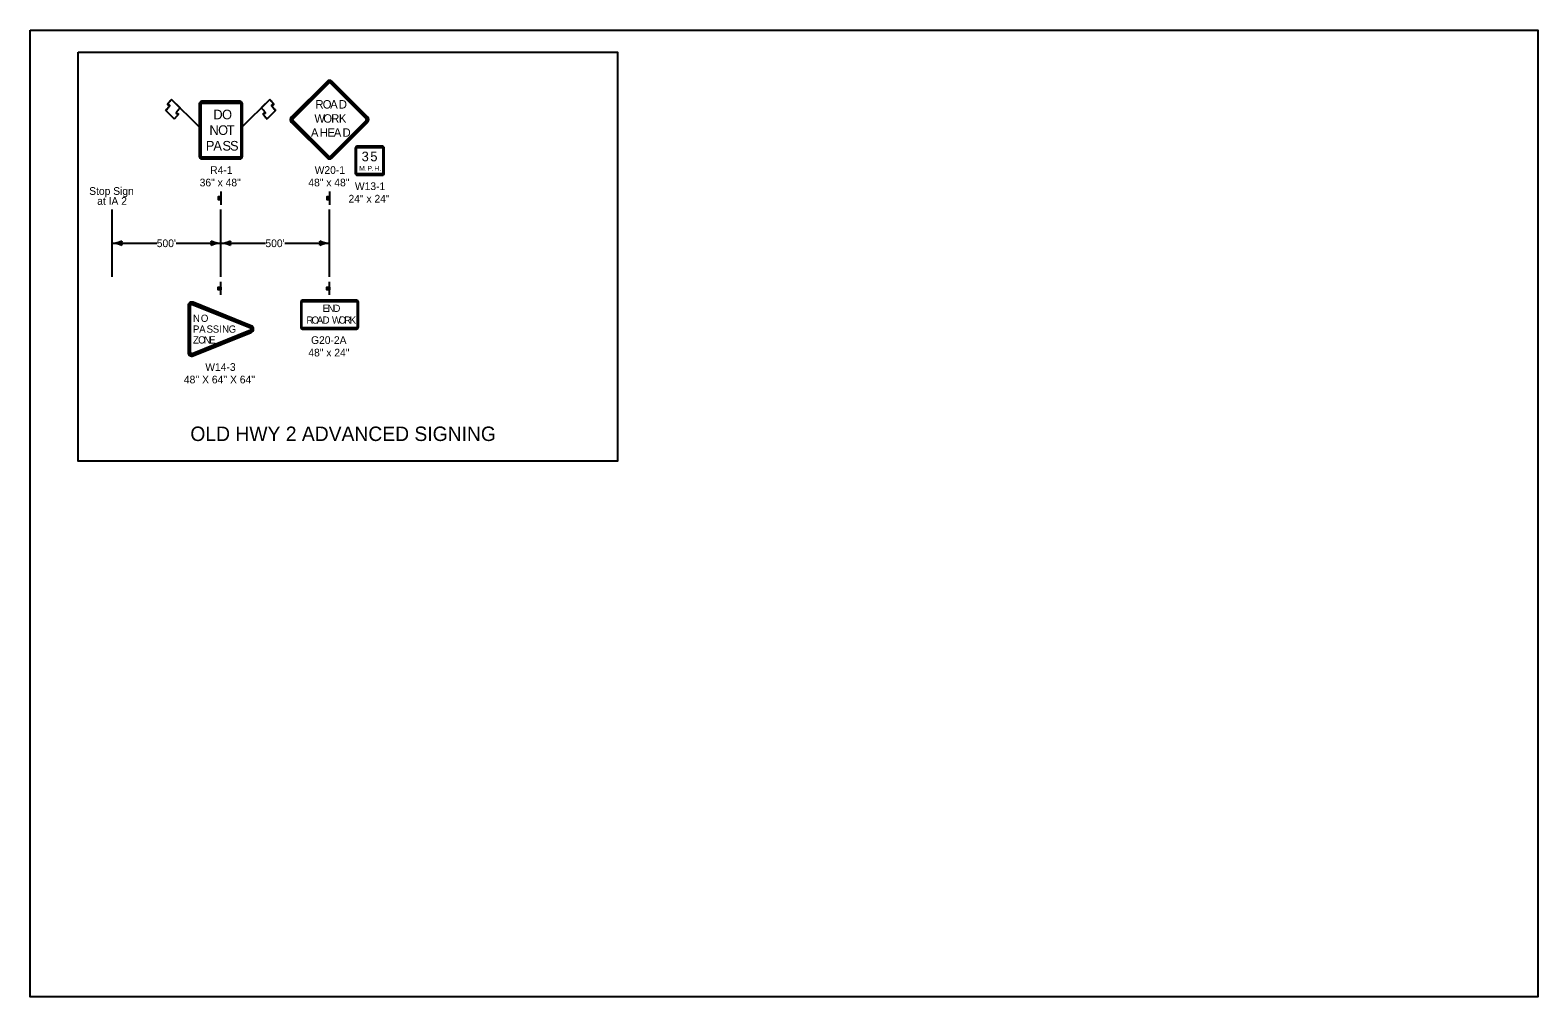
# Model space of a CAD drawing. Extents: x -2134934 to -2119606, y -2139046 to -2137036.
# Drawn here: x -2125529 to -2122394, y -2139046 to -2137036 of the extents above; entities that cross this region are included whole.
import ezdxf

# ---------------------------------------------------------------- set-up
doc = ezdxf.new("R2010")
doc.units = 0
for name, color, linetype in [('Default', 7, 'Continuous'), ('dsnStdLabel', 7, 'Continuous'), ('Level 2', 7, 'Continuous'), ('Level 5', 7, 'Continuous')]:
    doc.layers.add(name, color=color, linetype=linetype)

msp = doc.modelspace()

# ---------------------------------------------------------------- linework, layer by layer
at = {"layer": 'Default'}
msp.add_lwpolyline([(-2125529.5, -2137035.9), (-2122394.5, -2137035.9), (-2122394.5, -2139045.9), (-2125529.5, -2139045.9)], close=True, dxfattribs=at)
at = {"layer": 'dsnStdLabel'}
for p, q in [((-2124912.2, -2137142.5), (-2124986.5, -2137216.7)), ((-2124910.9, -2137143.8), (-2124908.7, -2137146)), ((-2124905.1, -2137146), (-2124902.9, -2137143.8)), ((-2124827.4, -2137216.7), (-2124901.6, -2137142.5)), ((-2125177.9, -2137237.3), (-2125235.3, -2137180)), ((-2125235.3, -2137180), (-2125217.6, -2137197.7)), ((-2125093.6, -2137183.8), (-2125172.3, -2137183.8)), ((-2125172.3, -2137187.5), (-2125172.3, -2137185.3)), ((-2125093.6, -2137185.3), (-2125093.6, -2137187.5)), ((-2125088.7, -2137237.3), (-2125031.3, -2137180)), ((-2125031.3, -2137180), (-2125049, -2137197.6)), ((-2125230, -2137220.6), (-2125247.6, -2137203)), ((-2125177.9, -2137189.4), (-2125177.9, -2137298.1)), ((-2125176.4, -2137189.4), (-2125174.2, -2137189.4)), ((-2125091.7, -2137189.4), (-2125089.5, -2137189.4)), ((-2125087.9, -2137298.1), (-2125087.9, -2137189.4)), ((-2125036.6, -2137220.6), (-2125019, -2137203)), ((-2124982.9, -2137220.2), (-2124985.1, -2137218)), ((-2124828.7, -2137218), (-2124830.9, -2137220.2)), ((-2124986.5, -2137227.3), (-2124912.2, -2137301.6)), ((-2124985.1, -2137226), (-2124982.9, -2137223.8)), ((-2124901.6, -2137301.6), (-2124827.4, -2137227.3)), ((-2124830.9, -2137223.8), (-2124828.7, -2137226)), ((-2124853.4, -2137281.2), (-2124853.4, -2137333.7)), ((-2124852.5, -2137281.2), (-2124850.9, -2137281.2)), ((-2124797.1, -2137277.4), (-2124849.6, -2137277.4)), ((-2124849.6, -2137279.9), (-2124849.6, -2137278.3)), ((-2124797.1, -2137278.3), (-2124797.1, -2137279.9)), ((-2124795.9, -2137281.2), (-2124794.3, -2137281.2)), ((-2124793.4, -2137333.7), (-2124793.4, -2137281.2)), ((-2125174.2, -2137298.1), (-2125176.4, -2137298.1)), ((-2125172.3, -2137302.2), (-2125172.3, -2137300)), ((-2125172.3, -2137303.8), (-2125093.6, -2137303.8)), ((-2125093.6, -2137300), (-2125093.6, -2137302.2)), ((-2125089.5, -2137298.1), (-2125091.7, -2137298.1)), ((-2124908.7, -2137298), (-2124910.9, -2137300.2)), ((-2124902.9, -2137300.2), (-2124905.1, -2137298)), ((-2124850.9, -2137333.7), (-2124852.5, -2137333.7)), ((-2124849.6, -2137336.5), (-2124849.6, -2137334.9)), ((-2124849.6, -2137337.4), (-2124797.1, -2137337.4)), ((-2124797.1, -2137334.9), (-2124797.1, -2137336.5)), ((-2124794.3, -2137333.7), (-2124795.9, -2137333.7)), ((-2125200.9, -2137608.7), (-2125200.9, -2137706.4)), ((-2125199, -2137608.7), (-2125195.9, -2137608.7)), ((-2125192.4, -2137606.3), (-2125191.2, -2137603.4)), ((-2125069.7, -2137650.6), (-2125190.5, -2137601.7)), ((-2124966.9, -2137601.2), (-2124966.9, -2137653.7)), ((-2124966, -2137601.2), (-2124964.4, -2137601.2)), ((-2124850.7, -2137597.4), (-2124963.2, -2137597.4)), ((-2124963.2, -2137599.9), (-2124963.2, -2137598.3)), ((-2124850.7, -2137598.3), (-2124850.7, -2137599.9)), ((-2124849.4, -2137601.2), (-2124847.8, -2137601.2)), ((-2124846.9, -2137653.7), (-2124846.9, -2137601.2)), ((-2125070.4, -2137652.3), (-2125071.6, -2137655.2)), ((-2124964.4, -2137653.7), (-2124966, -2137653.7)), ((-2124963.2, -2137656.5), (-2124963.2, -2137654.9)), ((-2124963.2, -2137657.4), (-2124850.7, -2137657.4)), ((-2124850.7, -2137654.9), (-2124850.7, -2137656.5)), ((-2124847.8, -2137653.7), (-2124849.4, -2137653.7)), ((-2125190.5, -2137713.4), (-2125069.7, -2137664.5)), ((-2125071.6, -2137659.8), (-2125070.4, -2137662.7)), ((-2125195.9, -2137706.4), (-2125199, -2137706.4)), ((-2125191.2, -2137711.6), (-2125192.4, -2137708.7))]:
    msp.add_line(p, q, dxfattribs=at)
for points in [[(-2125429.5, -2137081.6), (-2124308.2, -2137081.6), (-2124308.2, -2137932.2), (-2125429.5, -2137932.2)], [(-2124910.9, -2137143.8), (-2124985.1, -2137218), (-2124982.9, -2137220.2), (-2124908.7, -2137146), (-2124910.9, -2137143.8)], [(-2124828.7, -2137218), (-2124902.9, -2137143.8), (-2124905.1, -2137146), (-2124830.9, -2137220.2), (-2124828.7, -2137218)], [(-2125093.6, -2137185.3), (-2125172.3, -2137185.3), (-2125172.3, -2137187.5), (-2125093.6, -2137187.5), (-2125093.6, -2137185.3)], [(-2125176.4, -2137189.4), (-2125176.4, -2137298.1), (-2125174.2, -2137298.1), (-2125174.2, -2137189.4), (-2125176.4, -2137189.4)], [(-2125089.5, -2137298.1), (-2125089.5, -2137189.4), (-2125091.7, -2137189.4), (-2125091.7, -2137298.1), (-2125089.5, -2137298.1)], [(-2124985.1, -2137226), (-2124910.9, -2137300.2), (-2124908.7, -2137298), (-2124982.9, -2137223.8), (-2124985.1, -2137226)], [(-2124902.9, -2137300.2), (-2124828.7, -2137226), (-2124830.9, -2137223.8), (-2124905.1, -2137298), (-2124902.9, -2137300.2)], [(-2124852.5, -2137281.2), (-2124852.5, -2137333.7), (-2124850.9, -2137333.7), (-2124850.9, -2137281.2), (-2124852.5, -2137281.2)], [(-2124797.1, -2137278.3), (-2124849.6, -2137278.3), (-2124849.6, -2137279.9), (-2124797.1, -2137279.9), (-2124797.1, -2137278.3)], [(-2124794.3, -2137333.7), (-2124794.3, -2137281.2), (-2124795.9, -2137281.2), (-2124795.9, -2137333.7), (-2124794.3, -2137333.7)], [(-2125172.3, -2137302.2), (-2125093.6, -2137302.2), (-2125093.6, -2137300), (-2125172.3, -2137300), (-2125172.3, -2137302.2)], [(-2124849.6, -2137336.5), (-2124797.1, -2137336.5), (-2124797.1, -2137334.9), (-2124849.6, -2137334.9), (-2124849.6, -2137336.5)], [(-2125199, -2137608.7), (-2125199, -2137706.4), (-2125195.9, -2137706.4), (-2125195.9, -2137608.7), (-2125199, -2137608.7)], [(-2125070.4, -2137652.3), (-2125191.2, -2137603.4), (-2125192.4, -2137606.3), (-2125071.6, -2137655.2), (-2125070.4, -2137652.3)], [(-2124966, -2137601.2), (-2124966, -2137653.7), (-2124964.4, -2137653.7), (-2124964.4, -2137601.2), (-2124966, -2137601.2)], [(-2124850.7, -2137598.3), (-2124963.2, -2137598.3), (-2124963.2, -2137599.9), (-2124850.7, -2137599.9), (-2124850.7, -2137598.3)], [(-2124847.8, -2137653.7), (-2124847.8, -2137601.2), (-2124849.4, -2137601.2), (-2124849.4, -2137653.7), (-2124847.8, -2137653.7)], [(-2124963.2, -2137656.5), (-2124850.7, -2137656.5), (-2124850.7, -2137654.9), (-2124963.2, -2137654.9), (-2124963.2, -2137656.5)], [(-2125191.2, -2137711.6), (-2125070.4, -2137662.7), (-2125071.6, -2137659.8), (-2125192.4, -2137708.7), (-2125191.2, -2137711.6)]]:
    msp.add_lwpolyline(points, close=True, dxfattribs=at)
for centre, radius, start, end in [((-2124906.9, -2137147.8), 7.5, 45, 134.9997), ((-2124906.9, -2137147.8), 5.62, 45, 134.9997), ((-2124906.9, -2137147.8), 2.5, 45, 134.9997), ((-2125172.3, -2137189.4), 5.62, 90.0002, 179.9998), ((-2125172.3, -2137189.4), 4.06, 90.0002, 179.9998), ((-2125172.3, -2137189.4), 1.87, 90.0002, 179.9998), ((-2125093.6, -2137189.4), 5.62, 0, 90.0002), ((-2125093.6, -2137189.4), 4.06, 0, 90.0002), ((-2125093.6, -2137189.4), 1.87, 0, 90.0002), ((-2124981.2, -2137222), 7.5, 134.9997, 225), ((-2124981.2, -2137222), 5.62, 134.9997, 225), ((-2124832.7, -2137222), 5.62, 315.0002, 44.9998), ((-2124832.7, -2137222), 7.5, 315.0002, 44.9998), ((-2124981.2, -2137222), 2.5, 134.9997, 225), ((-2124832.7, -2137222), 2.5, 315.0002, 44.9998), ((-2124849.6, -2137281.2), 3.75, 90.0002, 179.9998), ((-2124849.6, -2137281.2), 2.81, 90.0002, 179.9998), ((-2124849.6, -2137281.2), 1.25, 90.0002, 179.9998), ((-2124797.1, -2137281.2), 3.75, 0, 90.0002), ((-2124797.1, -2137281.2), 2.81, 0, 90.0002), ((-2124797.1, -2137281.2), 1.25, 0, 90.0002), ((-2125172.3, -2137298.1), 5.62, 179.9998, 270.0001), ((-2125172.3, -2137298.1), 4.06, 179.9998, 270.0001), ((-2125172.3, -2137298.1), 1.87, 179.9998, 270.0001), ((-2125093.6, -2137298.1), 5.62, 270.0001, 0.0003), ((-2125093.6, -2137298.1), 4.06, 270.0001, 0.0003), ((-2125093.6, -2137298.1), 1.87, 270.0001, 0.0003), ((-2124906.9, -2137296.3), 7.5, 225, 315.0002), ((-2124906.9, -2137296.3), 5.62, 225, 315.0002), ((-2124906.9, -2137296.3), 2.5, 225, 315.0002), ((-2124849.6, -2137333.7), 3.75, 179.9998, 270.0001), ((-2124849.6, -2137333.7), 2.81, 179.9998, 270.0001), ((-2124849.6, -2137333.7), 1.25, 179.9998, 270.0001), ((-2124797.1, -2137333.7), 3.75, 270.0001, 0.0003), ((-2124797.1, -2137333.7), 2.81, 270.0001, 0.0003), ((-2124797.1, -2137333.7), 1.25, 270.0001, 0.0003), ((-2125193.4, -2137608.7), 7.5, 67.9757, 179.9998), ((-2125193.4, -2137608.7), 5.62, 67.9757, 179.9998), ((-2125193.4, -2137608.7), 2.5, 67.9757, 179.9998), ((-2124963.2, -2137601.2), 3.75, 90.0002, 179.9998), ((-2124963.2, -2137601.2), 2.81, 90.0002, 179.9998), ((-2124963.2, -2137601.2), 1.25, 90.0002, 179.9998), ((-2124850.7, -2137601.2), 3.75, 0, 90.0002), ((-2124850.7, -2137601.2), 2.81, 0, 90.0002), ((-2124850.7, -2137601.2), 1.25, 0, 90.0002), ((-2125072.5, -2137657.5), 2.5, 292.0246, 67.9754), ((-2125072.5, -2137657.5), 5.62, 292.0246, 67.9754), ((-2125072.5, -2137657.5), 7.5, 292.0246, 67.976), ((-2124963.2, -2137653.7), 3.75, 179.9998, 270.0001), ((-2124963.2, -2137653.7), 2.81, 179.9998, 270.0001), ((-2124963.2, -2137653.7), 1.25, 179.9998, 270.0001), ((-2124850.7, -2137653.7), 3.75, 270.0001, 0.0003), ((-2124850.7, -2137653.7), 2.81, 270.0001, 0.0003), ((-2124850.7, -2137653.7), 1.25, 270.0001, 0.0003), ((-2125193.4, -2137706.4), 7.5, 179.9998, 292.0246), ((-2125193.4, -2137706.4), 5.62, 179.9998, 292.0246), ((-2125193.4, -2137706.4), 2.5, 179.9998, 292.0246)]:
    msp.add_arc(centre, radius, start, end, dxfattribs=at)
for points in [[(-2125247.6, -2137203), (-2125235.3, -2137190.6), (-2125247.7, -2137192.4), (-2125235.3, -2137180)], [(-2125019, -2137203), (-2125031.3, -2137190.6), (-2125019, -2137192.3), (-2125031.3, -2137180)], [(-2125217.6, -2137197.7), (-2125230, -2137210), (-2125217.6, -2137208.3), (-2125230, -2137220.6)], [(-2125049, -2137197.6), (-2125036.6, -2137210), (-2125049, -2137208.3), (-2125036.6, -2137220.6)]]:
    msp.add_open_spline(points, degree=2, dxfattribs=at)
at = {"layer": 'Level 2'}
for p, q in [((-2125132.9, -2137371.6), (-2125132.9, -2137399.1)), ((-2124906.9, -2137371.6), (-2124906.9, -2137399.1)), ((-2125138.3, -2137382.4), (-2125138.3, -2137388)), ((-2125138, -2137388), (-2125138, -2137382.4)), ((-2125137.7, -2137382.4), (-2125137.7, -2137388)), ((-2125137.4, -2137388), (-2125137.4, -2137382.4)), ((-2125137.2, -2137382.4), (-2125137.2, -2137388)), ((-2125136.8, -2137388), (-2125136.8, -2137382.4)), ((-2125136.5, -2137382.4), (-2125136.5, -2137388)), ((-2125136.1, -2137388), (-2125136.1, -2137382.4)), ((-2125135.7, -2137382.4), (-2125135.7, -2137388)), ((-2125135.4, -2137388), (-2125135.4, -2137382.4)), ((-2125135.2, -2137382.4), (-2125135.2, -2137388)), ((-2125134.9, -2137388), (-2125134.9, -2137382.4)), ((-2125134.6, -2137382.4), (-2125134.6, -2137388)), ((-2125134.4, -2137388), (-2125134.4, -2137382.4)), ((-2125134.2, -2137382.4), (-2125134.2, -2137388)), ((-2125133.9, -2137388), (-2125133.9, -2137382.4)), ((-2125133.6, -2137382.4), (-2125133.6, -2137388)), ((-2125133.4, -2137388), (-2125133.4, -2137382.4)), ((-2124912.2, -2137382.4), (-2124912.2, -2137388)), ((-2124911.9, -2137388), (-2124911.9, -2137382.4)), ((-2124911.7, -2137382.4), (-2124911.7, -2137388)), ((-2124911.4, -2137388), (-2124911.4, -2137382.4)), ((-2124911.1, -2137382.4), (-2124911.2, -2137388)), ((-2124910.7, -2137388), (-2124910.7, -2137382.4)), ((-2124910.5, -2137382.4), (-2124910.5, -2137388)), ((-2124910.1, -2137388), (-2124910.1, -2137382.4)), ((-2124909.7, -2137382.4), (-2124909.7, -2137388)), ((-2124909.4, -2137388), (-2124909.4, -2137382.4)), ((-2124909.2, -2137382.4), (-2124909.2, -2137388)), ((-2124908.9, -2137388), (-2124908.9, -2137382.4)), ((-2124908.6, -2137382.4), (-2124908.6, -2137388)), ((-2124908.4, -2137388), (-2124908.4, -2137382.4)), ((-2124908.1, -2137382.4), (-2124908.1, -2137388)), ((-2124907.9, -2137388), (-2124907.9, -2137382.4)), ((-2124907.6, -2137382.4), (-2124907.6, -2137388)), ((-2124907.3, -2137388), (-2124907.3, -2137382.4)), ((-2125359, -2137549.1), (-2125359, -2137409.1)), ((-2125132.9, -2137549.1), (-2125132.9, -2137409.1)), ((-2124906.9, -2137549.1), (-2124906.9, -2137409.1)), ((-2125359, -2137479.1), (-2125266.2, -2137479.1)), ((-2125225.7, -2137479.1), (-2125132.9, -2137479.1)), ((-2125132.9, -2137479.1), (-2125040.2, -2137479.1)), ((-2124999.7, -2137479.1), (-2124906.9, -2137479.1)), ((-2125132.9, -2137586.6), (-2125132.9, -2137559.1)), ((-2124906.9, -2137586.6), (-2124906.9, -2137559.1)), ((-2125138.3, -2137575.7), (-2125138.3, -2137570.1)), ((-2125138, -2137570.1), (-2125138, -2137575.7)), ((-2125137.7, -2137575.7), (-2125137.7, -2137570.1)), ((-2125137.4, -2137570.1), (-2125137.4, -2137575.7)), ((-2125137.2, -2137575.7), (-2125137.2, -2137570.1)), ((-2125136.8, -2137570.1), (-2125136.8, -2137575.7)), ((-2125136.5, -2137575.7), (-2125136.5, -2137570.1)), ((-2125136.1, -2137570.1), (-2125136.1, -2137575.7)), ((-2125135.7, -2137575.7), (-2125135.7, -2137570.1)), ((-2125135.4, -2137570.1), (-2125135.4, -2137575.7)), ((-2125135.2, -2137575.7), (-2125135.2, -2137570.1)), ((-2125134.9, -2137570.1), (-2125134.9, -2137575.7)), ((-2125134.6, -2137575.7), (-2125134.6, -2137570.1)), ((-2125134.4, -2137570.1), (-2125134.4, -2137575.7)), ((-2125134.2, -2137575.7), (-2125134.2, -2137570.1)), ((-2125133.9, -2137570.1), (-2125133.9, -2137575.7)), ((-2125133.6, -2137575.7), (-2125133.6, -2137570.1)), ((-2125133.4, -2137570.1), (-2125133.4, -2137575.7)), ((-2124912.2, -2137575.7), (-2124912.2, -2137570.1)), ((-2124911.9, -2137570.1), (-2124911.9, -2137575.7)), ((-2124911.7, -2137575.7), (-2124911.7, -2137570.1)), ((-2124911.4, -2137570.1), (-2124911.4, -2137575.7)), ((-2124911.1, -2137575.7), (-2124911.2, -2137570.1)), ((-2124910.7, -2137570.1), (-2124910.7, -2137575.7)), ((-2124910.5, -2137575.7), (-2124910.5, -2137570.1)), ((-2124910.1, -2137570.1), (-2124910.1, -2137575.7)), ((-2124909.7, -2137575.7), (-2124909.7, -2137570.1)), ((-2124909.4, -2137570.1), (-2124909.4, -2137575.7)), ((-2124909.2, -2137575.7), (-2124909.2, -2137570.1)), ((-2124908.9, -2137570.1), (-2124908.9, -2137575.7)), ((-2124908.6, -2137575.7), (-2124908.6, -2137570.1)), ((-2124908.4, -2137570.1), (-2124908.4, -2137575.7)), ((-2124908.1, -2137575.7), (-2124908.1, -2137570.1)), ((-2124907.9, -2137570.1), (-2124907.9, -2137575.7)), ((-2124907.6, -2137575.7), (-2124907.6, -2137570.1)), ((-2124907.3, -2137570.1), (-2124907.3, -2137575.7))]:
    msp.add_line(p, q, dxfattribs=at)
for points in [[(-2125133, -2137388), (-2125133, -2137382.4), (-2125138.7, -2137382.4), (-2125138.7, -2137388)], [(-2124907, -2137388), (-2124907, -2137382.4), (-2124912.6, -2137382.4), (-2124912.6, -2137388)], [(-2125133, -2137570.1), (-2125133, -2137575.8), (-2125138.7, -2137575.8), (-2125138.7, -2137570.1)], [(-2124907, -2137570.1), (-2124907, -2137575.8), (-2124912.6, -2137575.8), (-2124912.6, -2137570.1)]]:
    msp.add_lwpolyline(points, close=True, dxfattribs=at)
for centre, radius, start, end in [((-2125359.7, -2137436.6), 42.5, 271.0176, 299.0725), ((-2125358.3, -2137521.6), 42.5, 62.9275, 90.9824), ((-2125323.4, -2137478.5), 16.4, 163.2666, 198.7334), ((-2125168.6, -2137478.5), 16.4, 341.2666, 16.7334), ((-2125133.7, -2137521.6), 42.5, 89.0176, 117.0725), ((-2125132.2, -2137436.6), 42.5, 240.9275, 268.9824), ((-2125133.7, -2137436.6), 42.5, 271.0176, 299.0725), ((-2125132.2, -2137521.6), 42.5, 62.9275, 90.9824), ((-2125097.3, -2137478.5), 16.4, 163.2666, 198.7334), ((-2124942.5, -2137478.5), 16.4, 341.2666, 16.7334), ((-2124907.6, -2137521.6), 42.5, 89.0176, 117.0725), ((-2124906.2, -2137436.6), 42.5, 240.9275, 268.9824)]:
    msp.add_arc(centre, radius, start, end, dxfattribs=at)
at = {"layer": 'Level 5'}
for p, q in [((-2125247.6, -2137203), (-2125230, -2137220.6)), ((-2125019, -2137203), (-2125036.6, -2137220.6))]:
    msp.add_line(p, q, dxfattribs=at)
for points in [[(-2125235.3, -2137180), (-2125247.7, -2137192.4), (-2125235.3, -2137190.6), (-2125247.6, -2137203)], [(-2125031.3, -2137180), (-2125019, -2137192.3), (-2125031.3, -2137190.6), (-2125019, -2137203)], [(-2125217.6, -2137197.7), (-2125230, -2137210), (-2125217.6, -2137208.3), (-2125230, -2137220.6)], [(-2125049, -2137197.6), (-2125036.6, -2137210), (-2125049, -2137208.3), (-2125036.6, -2137220.6)]]:
    msp.add_open_spline(points, degree=2, dxfattribs=at)

# ---------------------------------------------------------------- texts
at = {"layer": 'dsnStdLabel'}
for s, height, p in [('R', 17.5, (-2124936.1, -2137198.9)), ('O', 17.5, (-2124921.1, -2137198.9)), ('A', 17.5, (-2124905.5, -2137198.9)), ('D', 17.5, (-2124887.6, -2137198.9)), ('D', 20, (-2125148.6, -2137221.3)), ('O', 20, (-2125130.4, -2137221.3)), ('W', 17.5, (-2124938.4, -2137228.3)), ('O', 17.5, (-2124919.8, -2137228.3)), ('R', 17.5, (-2124903.4, -2137228.3)), ('K', 17.5, (-2124887.5, -2137228.3)), ('N', 20, (-2125156.7, -2137253.8)), ('O', 20, (-2125138.6, -2137253.8)), ('T', 20, (-2125120.8, -2137253.8)), ('A', 17.5, (-2124945.6, -2137257.6)), ('H', 17.5, (-2124927.4, -2137257.6)), ('E', 17.5, (-2124911.2, -2137257.6)), ('A', 17.5, (-2124898.1, -2137257.6)), ('D', 17.5, (-2124879.9, -2137257.6)), ('P', 20, (-2125164.2, -2137286.3)), ('A', 20, (-2125148.5, -2137286.3)), ('S', 20, (-2125129.6, -2137286.3)), ('S', 20, (-2125113.9, -2137286.3)), ('3', 20, (-2124840.2, -2137308.6)), ('5', 20, (-2124822.1, -2137308.6)), ('36" x 48"', 16, (-2125177, -2137360.8)), ('R4-1', 16, (-2125155.1, -2137334.8)), ('48" x 48"', 16, (-2124951, -2137360.8)), ('W20-1', 16, (-2124937.8, -2137334.8)), ('M', 10, (-2124845.2, -2137328.3)), ('.', 10, (-2124833.4, -2137328.3)), ('P', 10, (-2124827.9, -2137328.3)), ('.', 10, (-2124819.3, -2137328.3)), ('H', 10, (-2124813.8, -2137328.3)), ('.', 10, (-2124803.3, -2137328.3)), ('W13-1', 16, (-2124854.2, -2137368.4)), ('24" x 24"', 16, (-2124867.5, -2137394.4)), ('E', 15, (-2124921.6, -2137621.8)), ('N', 15, (-2124911, -2137621.8)), ('D', 15, (-2124898.9, -2137621.8)), ('N', 15, (-2125190.9, -2137642.5)), ('P', 15, (-2125190.9, -2137665)), ('A', 15, (-2125178, -2137665)), ('O', 15, (-2125174.5, -2137642.5)), ('S', 15, (-2125162.6, -2137665)), ('S', 15, (-2125149.8, -2137665)), ('I', 15, (-2125136.2, -2137665)), ('N', 15, (-2125130.3, -2137665)), ('G', 15, (-2125116.7, -2137665)), ('R', 15, (-2124955, -2137646.2)), ('O', 15, (-2124944.4, -2137646.2)), ('A', 15, (-2124933.2, -2137646.2)), ('D', 15, (-2124921.3, -2137646.2)), ('W', 15, (-2124901.9, -2137646.2)), ('O', 15, (-2124888.2, -2137646.2)), ('R', 15, (-2124876.4, -2137646.2)), ('K', 15, (-2124865.1, -2137646.2)), ('Z', 15, (-2125190.9, -2137687.5)), ('O', 15, (-2125180.2, -2137687.5)), ('N', 15, (-2125168.3, -2137687.5)), ('E', 15, (-2125157, -2137687.5)), ('G20-2A', 16, (-2124945.4, -2137688.4)), ('48" x 24"', 16, (-2124951, -2137714.4)), ('W14-3', 16, (-2125165.3, -2137744.4)), ("48'' X 64'' X 64''", 16, (-2125209.8, -2137770.4)), ('OLD HWY 2 ADVANCED SIGNING', 30, (-2125196.3, -2137890.2))]:
    msp.add_text(s, height=height, dxfattribs=at).set_placement(p)
at = {"layer": 'Level 2'}
for s, p in [('Stop Sign', (-2125406.7, -2137378.4)), ('at IA 2', (-2125390.1, -2137399.1)), ("500'", (-2125266.2, -2137487.1)), ("500'", (-2125040.2, -2137487.1))]:
    msp.add_text(s, height=16, dxfattribs=at).set_placement(p)

doc.saveas('drawing.dxf')
